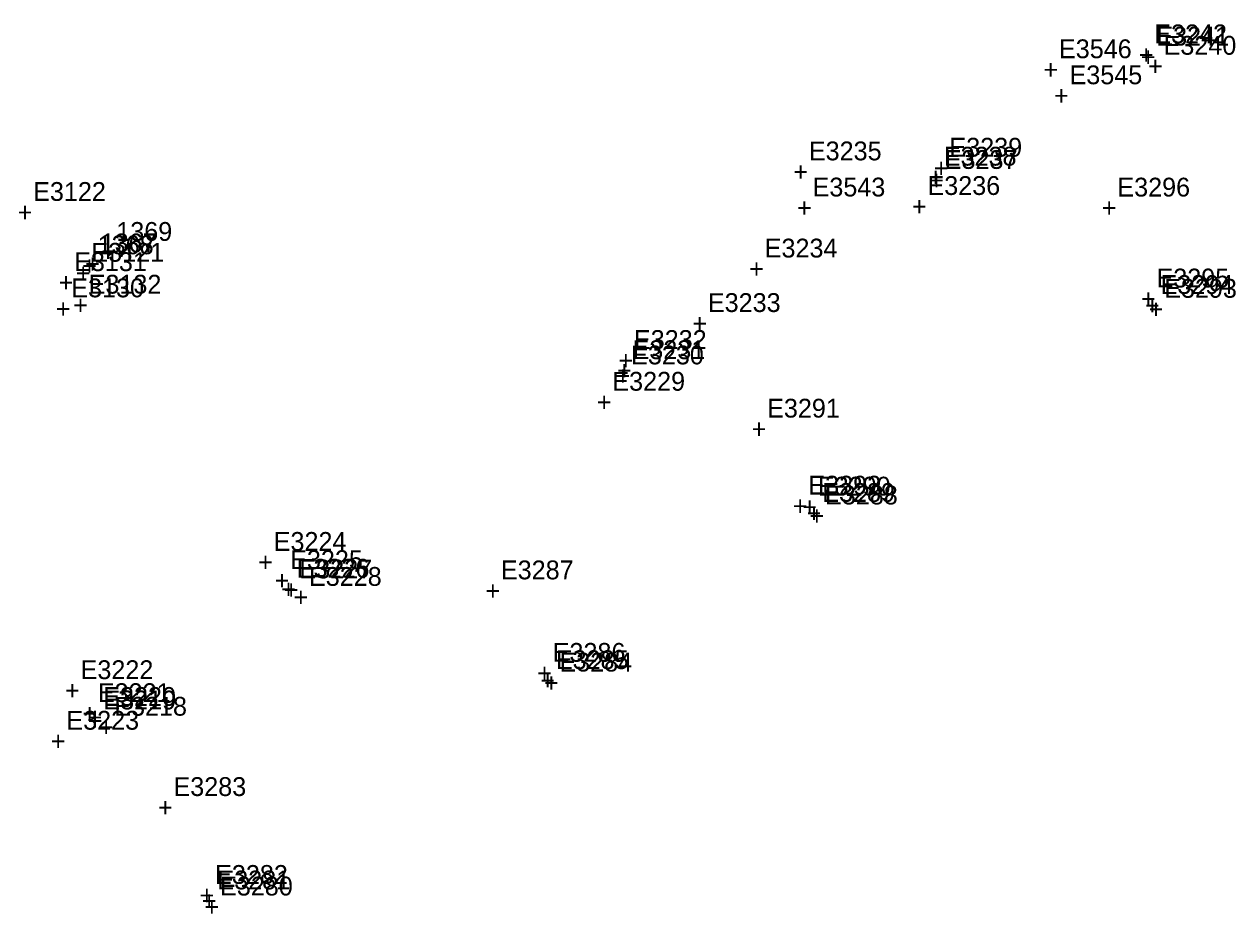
# Model space of a CAD drawing. Extents: x 1667192 to 1669644, y 336680 to 339991.
# Drawn here: x 1668335.8 to 1668496.8, y 339436.9 to 339555 of the extents above; entities that cross this region are included whole.
import ezdxf

# ---------------------------------------------------------------- set-up
doc = ezdxf.new("R2010")
doc.units = 0
for name, color, linetype in [('S_Curb_Type_1', 7, 'Continuous'), ('S_Curb_Type_5', 7, 'Continuous'), ('S_Drainage_CB', 7, 'Continuous'), ('S_Ground_Elevation', 7, 'Continuous'), ('S_Guardrail_Beam', 7, 'Continuous'), ('S_Roadway_Edge_Pavement', 7, 'Continuous'), ('S_Roadway_Edge_TW', 7, 'Continuous'), ('S_Traffic_Sign_SinglePost', 7, 'Continuous')]:
    doc.layers.add(name, color=color, linetype=linetype)

msp = doc.modelspace()

# ---------------------------------------------------------------- texts
at = {"layer": 'S_Curb_Type_1'}
for s, p in [('E3242', (1668485.99, 339552.51)), ('+', (1668483.93, 339549.76)), ('E3238', (1668458.01, 339536.26)), ('+', (1668455.95, 339533.51)), ('1368', (1668345.56, 339524.48)), ('+', (1668343.5, 339521.73)), ('E3226', (1668372.01, 339481.51)), ('+', (1668369.95, 339478.76)), ('E3220', (1668346.29, 339464.47)), ('+', (1668344.22, 339461.72))]:
    msp.add_text(s, height=2.5, dxfattribs=at).set_placement(p)
at = {"layer": 'S_Curb_Type_5'}
for s, p in [('E3293', (1668487.3, 339518.7)), ('+', (1668485.24, 339515.95)), ('E3288', (1668442.23, 339491.24)), ('+', (1668440.17, 339488.49)), ('E3284', (1668406.93, 339469.04)), ('+', (1668404.87, 339466.29)), ('E3280', (1668361.82, 339439.28)), ('+', (1668359.76, 339436.53))]:
    msp.add_text(s, height=2.5, dxfattribs=at).set_placement(p)
at = {"layer": 'S_Drainage_CB'}
for s, p in [('E3292', (1668440.01, 339492.55)), ('+', (1668437.95, 339489.8))]:
    msp.add_text(s, height=2.5, dxfattribs=at).set_placement(p)
at = {"layer": 'S_Ground_Elevation'}
for s, p in [('E3546', (1668473.32, 339550.53)), ('+', (1668471.25, 339547.78)), ('E3545', (1668474.72, 339547.07)), ('+', (1668472.66, 339544.32)), ('E3239', (1668458.76, 339537.45)), ('+', (1668456.7, 339534.7)), ('E3122', (1668336.98, 339531.57)), ('E3543', (1668440.57, 339532.16)), ('+', (1668334.92, 339528.82)), ('+', (1668438.51, 339529.41)), ('E3121', (1668344.72, 339523.49)), ('E3131', (1668342.43, 339522.24)), ('+', (1668342.66, 339520.74)), ('+', (1668340.37, 339519.49)), ('E3132', (1668344.36, 339519.25)), ('+', (1668342.3, 339516.5)), ('E3232', (1668416.83, 339511.9)), ('+', (1668414.77, 339509.15)), ('E3224', (1668368.95, 339485.07)), ('+', (1668366.89, 339482.32)), ('E3225', (1668371.14, 339482.65)), ('+', (1668369.08, 339479.9)), ('E3222', (1668343.29, 339468.03)), ('+', (1668341.22, 339465.29)), ('E3221', (1668345.58, 339464.98)), ('+', (1668343.52, 339462.23))]:
    msp.add_text(s, height=2.5, dxfattribs=at).set_placement(p)
at = {"layer": 'S_Guardrail_Beam'}
for s, p in [('E3235', (1668440.08, 339536.96)), ('+', (1668438.02, 339534.21)), ('E3234', (1668434.21, 339524.05)), ('+', (1668432.15, 339521.3)), ('E3233', (1668426.66, 339516.81)), ('+', (1668424.6, 339514.06)), ('E3231', (1668416.64, 339510.55)), ('+', (1668414.58, 339507.8)), ('E3223', (1668341.4, 339461.31)), ('+', (1668339.34, 339458.56))]:
    msp.add_text(s, height=2.5, dxfattribs=at).set_placement(p)
at = {"layer": 'S_Roadway_Edge_Pavement'}
for s, p in [('E3241', (1668486.26, 339552.21)), ('+', (1668484.2, 339549.46)), ('E3237', (1668458.14, 339535.82)), ('+', (1668456.08, 339533.07)), ('1367', (1668345.96, 339524.74)), ('+', (1668343.9, 339521.99)), ('E3294', (1668486.81, 339519.21)), ('+', (1668484.75, 339516.46)), ('E3230', (1668416.45, 339509.85)), ('+', (1668414.39, 339507.1)), ('E3289', (1668441.86, 339491.58)), ('+', (1668439.79, 339488.83)), ('E3227', (1668372.37, 339481.41)), ('+', (1668370.31, 339478.66)), ('E3285', (1668406.45, 339469.36)), ('+', (1668404.39, 339466.61)), ('E3219', (1668346.31, 339464)), ('+', (1668344.25, 339461.25)), ('E3281', (1668361.47, 339440.09)), ('+', (1668359.41, 339437.34))]:
    msp.add_text(s, height=2.5, dxfattribs=at).set_placement(p)
at = {"layer": 'S_Roadway_Edge_TW'}
for s, p in [('E3240', (1668487.22, 339550.99)), ('+', (1668485.16, 339548.24)), ('E3236', (1668455.84, 339532.36)), ('E3296', (1668481.08, 339532.15)), ('+', (1668453.78, 339529.61)), ('+', (1668479.02, 339529.4)), ('1369', (1668348.03, 339526.26)), ('+', (1668345.96, 339523.51)), ('E3295', (1668486.28, 339520.07)), ('+', (1668484.22, 339517.32)), ('E3229', (1668413.96, 339506.35)), ('+', (1668411.9, 339503.6)), ('E3291', (1668434.53, 339502.78)), ('+', (1668432.47, 339500.03)), ('E3290', (1668441.27, 339492.42)), ('+', (1668439.21, 339489.67)), ('E3287', (1668399.15, 339481.29)), ('E3228', (1668373.64, 339480.42)), ('+', (1668397.09, 339478.54)), ('+', (1668371.58, 339477.67)), ('E3286', (1668406.03, 339470.33)), ('+', (1668403.97, 339467.58)), ('E3218', (1668347.76, 339463.17)), ('+', (1668345.7, 339460.43)), ('E3283', (1668355.63, 339452.5)), ('+', (1668353.57, 339449.75)), ('E3282', (1668361.16, 339440.82)), ('+', (1668359.1, 339438.07))]:
    msp.add_text(s, height=2.5, dxfattribs=at).set_placement(p)
at = {"layer": 'S_Traffic_Sign_SinglePost'}
for s, p in [('E3130', (1668342.05, 339518.76)), ('+', (1668339.99, 339516.01))]:
    msp.add_text(s, height=2.5, dxfattribs=at).set_placement(p)

doc.saveas('drawing.dxf')
